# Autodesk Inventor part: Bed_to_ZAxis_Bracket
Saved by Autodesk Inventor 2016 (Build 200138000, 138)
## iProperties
Created: 2015-11
Part Number: Bed_to_ZAxis_Bracket
Material: Generic
Document SubType Name: Modeling
Designer: John
Density: 1 g/cm^3
Appearance: Default
Author: John
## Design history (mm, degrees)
feature "Base1"
body "Solid1"
